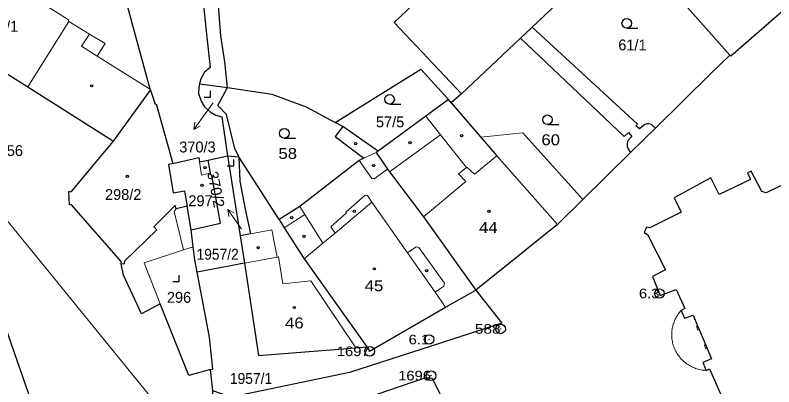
# Model space of a CAD drawing. Extents: x -679733 to -673243, y -1075091 to -1066557.
# Drawn here: x -676657.5 to -676538.9, y -1071507.3 to -1071449.2 of the extents above; entities that cross this region are included whole.
import ezdxf
from ezdxf.enums import TextEntityAlignment as Align

# ---------------------------------------------------------------- set-up
doc = ezdxf.new("R2010")
doc.units = 0
doc.header["$LTSCALE"] = 0.68
for name, color, linetype, lineweight in [('1', 7, 'Continuous', 25), ('13', 7, 'Continuous', 13), ('3', 7, 'Continuous', 25), ('4', 7, 'Continuous', 13), ('5', 7, 'Continuous', 25), ('7', 7, 'Continuous', 13), ('8', 7, 'Continuous', 25)]:
    doc.layers.add(name, color=color, linetype=linetype, lineweight=lineweight)
doc.layers.add('2', color=7, linetype='Continuous')

msp = doc.modelspace()

# ---------------------------------------------------------------- linework, layer by layer
at = {"layer": '1'}
for p, q in [((-676628.73, -1071459.98), (-676624.32, -1071460.51)), ((-676642.15, -1071468.89), (-676636.38, -1071460.95)), ((-676589.38, -1071462.9), (-676589.79, -1071462.4)), ((-676587.79, -1071461.53), (-676589.38, -1071462.9)), ((-676606.31, -1071466.64), (-676607.51, -1071466)), ((-676561.31, -1071470.64), (-676557.42, -1071466.86)), ((-676627.36, -1071471.86), (-676624.35, -1071471.19)), ((-676624.35, -1071471.19), (-676622.36, -1071483.7)), ((-676616.29, -1071481.17), (-676622.56, -1071471.37)), ((-676572.75, -1071481.92), (-676585.53, -1071492.18)), ((-676622.36, -1071483.7), (-676621.71, -1071487.97)), ((-676621.71, -1071487.97), (-676629.08, -1071489.37))]:
    msp.add_line(p, q, dxfattribs=at)
for points in [[(-676575.21, -1071422.22), (-676585.95, -1071432.82), (-676589.88, -1071436.78), (-676588.71, -1071438.04), (-676592.2, -1071441.42), (-676590.62, -1071443.1), (-676592.88, -1071445.22), (-676594.32, -1071443.69), (-676596.77, -1071446.05), (-676595.33, -1071447.58), (-676598.3, -1071450.36), (-676587.79, -1071461.53)], [(-676624.32, -1071460.51), (-676624.77, -1071456.53), (-676625.37, -1071452.45), (-676625.93, -1071445.76), (-676626.71, -1071437.13), (-676627.11, -1071434.06), (-676627.22, -1071431), (-676625.45, -1071424.7), (-676629.15, -1071423.95), (-676629.99, -1071425.14)], [(-676629.99, -1071425.14), (-676626.5, -1071425.54), (-676627.51, -1071429.11), (-676631.18, -1071428.42), (-676629.85, -1071430.36), (-676627.63, -1071452.18), (-676627.06, -1071457.4), (-676627.95, -1071458.12), (-676628.5, -1071459.17), (-676628.73, -1071459.98)], [(-676636.38, -1071460.95), (-676636.42, -1071460.8), (-676642.28, -1071439.33), (-676642.84, -1071437.27)], [(-676545.82, -1071455.5), (-676555.33, -1071444.77), (-676560.86, -1071438.5), (-676561.02, -1071438.3)], [(-676557.42, -1071466.86), (-676557.95, -1071466.4), (-676558.07, -1071466.32), (-676558.3, -1071466.23), (-676558.56, -1071466.19), (-676558.82, -1071466.22), (-676559.09, -1071466.31), (-676559.32, -1071466.47), (-676559.94, -1071467.01), (-676560.51, -1071466.49), (-676560.28, -1071466.24), (-676576.7, -1071451.11), (-676570.92, -1071445.57), (-676569.45, -1071444.14), (-676566.87, -1071441.72)], [(-676683.31, -1071443.03), (-676678.47, -1071446), (-676678.32, -1071445.78), (-676677.41, -1071446.35), (-676671.78, -1071449.97), (-676667.98, -1071452.47), (-676668.07, -1071452.62), (-676659.58, -1071457.99), (-676659.52, -1071457.9), (-676655.53, -1071460.4), (-676642.15, -1071468.89)], [(-676706.46, -1071448.39), (-676704.76, -1071448.03), (-676703.73, -1071447.81), (-676701.26, -1071447.54), (-676698.72, -1071447.92), (-676696.46, -1071448.78), (-676694.26, -1071449.98), (-676691.89, -1071451.57), (-676693.28, -1071454.07), (-676687.45, -1071458.85), (-676678.05, -1071467.82), (-676669.42, -1071477.57), (-676664.74, -1071483.89), (-676662.51, -1071488.58), (-676660.71, -1071493.4), (-676651.25, -1071520.53)], [(-676536.58, -1071447.6), (-676536.53, -1071447.7), (-676545.68, -1071455.62), (-676545.82, -1071455.5)], [(-676587.79, -1071461.53), (-676578.53, -1071452.8), (-676562.35, -1071468.16), (-676561.69, -1071467.58), (-676561.13, -1071468.18), (-676561.69, -1071468.71), (-676561.83, -1071469.03), (-676561.87, -1071469.31), (-676561.86, -1071469.73), (-676561.72, -1071470.13), (-676561.5, -1071470.46), (-676561.31, -1071470.64)], [(-676557.42, -1071466.86), (-676548.86, -1071458.37), (-676545.82, -1071455.5)], [(-676607.51, -1071466), (-676594.11, -1071457.66), (-676589.79, -1071462.4)], [(-676628.73, -1071459.98), (-676628.82, -1071460.51), (-676628.88, -1071461.45), (-676628.47, -1071462.65), (-676627.94, -1071463.57), (-676627.05, -1071464.32), (-676626.16, -1071464.83), (-676625.23, -1071465.11), (-676624.35, -1071471.19), (-676622.56, -1071471.37)], [(-676636.38, -1071460.95), (-676635.66, -1071463.14), (-676635.48, -1071463.1), (-676632.91, -1071472.41)], [(-676622.56, -1071471.37), (-676623.2, -1071470.06), (-676624.52, -1071464.72), (-676625.83, -1071463.35), (-676624.32, -1071460.51)], [(-676624.32, -1071460.51), (-676617.41, -1071461.57), (-676612.04, -1071463.56), (-676607.51, -1071466)], [(-676589.79, -1071462.4), (-676593.35, -1071465.01), (-676600.82, -1071470.47)], [(-676589.38, -1071462.9), (-676582.24, -1071471.2), (-676572.75, -1071481.92), (-676561.31, -1071470.64)], [(-676606.31, -1071466.64), (-676607.49, -1071468.2), (-676603.03, -1071471.58), (-676603.76, -1071471.92), (-676613.06, -1071479.12), (-676616.29, -1071481.17)], [(-676600.82, -1071470.47), (-676601.26, -1071470.14), (-676606.31, -1071466.64)], [(-676640.98, -1071488.07), (-676640.98, -1071487.71), (-676648.75, -1071478.84), (-676649.05, -1071478.85), (-676649.16, -1071476.79), (-676648.75, -1071476.77), (-676642.15, -1071468.89)], [(-676600.82, -1071470.47), (-676601.13, -1071470.7), (-676599.31, -1071473.3), (-676599.02, -1071473.71), (-676593.72, -1071480.71), (-676585.53, -1071492.18)], [(-676632.91, -1071472.41), (-676628.82, -1071471.47), (-676628.71, -1071472.16), (-676627.36, -1071471.86)], [(-676630.02, -1071482.74), (-676625.44, -1071481.71), (-676626.79, -1071474.25), (-676626.95, -1071474.15), (-676627.36, -1071471.86)], [(-676622.56, -1071471.37), (-676622.4, -1071475.15), (-676621.6, -1071479.52), (-676620.73, -1071483.38), (-676622.36, -1071483.7)], [(-676632.91, -1071472.41), (-676633.59, -1071472.56), (-676632.83, -1071476.98), (-676631.07, -1071476.67), (-676630.65, -1071479.08)], [(-676535.46, -1071474.69), (-676540.14, -1071476.96), (-676540.83, -1071476.76), (-676542.48, -1071473.58), (-676543.09, -1071473.88), (-676542.6, -1071474.91), (-676547.5, -1071477.26), (-676548.79, -1071474.64), (-676554.53, -1071477.75), (-676553.41, -1071480.02), (-676558.35, -1071482.47), (-676558.83, -1071482.37), (-676559.21, -1071483.18), (-676558.7, -1071483.47), (-676555.88, -1071489.02), (-676557.91, -1071490.05), (-676556.69, -1071493.04), (-676554.21, -1071492.06), (-676552.88, -1071495.05), (-676553.44, -1071495.37), (-676552.91, -1071496.58), (-676551.58, -1071496.09), (-676550.88, -1071497.75), (-676550.62, -1071498.35), (-676549.63, -1071500.7), (-676549.38, -1071501.29), (-676548.69, -1071502.91), (-676550.04, -1071503.48), (-676549.55, -1071504.72), (-676548.98, -1071504.49), (-676546.37, -1071510.5)], [(-676630.65, -1071479.08), (-676632.38, -1071479.48), (-676632.51, -1071478.95), (-676635.87, -1071482.28), (-676635.41, -1071482.76), (-676640.47, -1071487.67), (-676640.56, -1071488.12), (-676640.98, -1071488.07)], [(-676629.08, -1071489.37), (-676629.44, -1071487.46), (-676629.69, -1071485.41), (-676630.02, -1071482.74), (-676630.65, -1071479.08)], [(-676616.29, -1071481.17), (-676615.48, -1071482.43), (-676612.36, -1071487.31), (-676602.56, -1071501.05)], [(-676627.01, -1071504.59), (-676630.37, -1071505.54), (-676634.87, -1071494.32), (-676637.78, -1071495.87), (-676640.61, -1071489.82), (-676640.98, -1071488.07)], [(-676621.71, -1071487.97), (-676619.51, -1071502.38), (-676604.26, -1071501.2), (-676602.56, -1071501.05)], [(-676627.01, -1071504.59), (-676626.63, -1071504.55), (-676627.15, -1071499.52), (-676629.08, -1071489.37)], [(-676585.53, -1071492.18), (-676581.49, -1071497.33), (-676590.88, -1071500.43), (-676605.28, -1071505.07), (-676623.79, -1071508.92), (-676626.66, -1071507.94)], [(-676602.56, -1071501.05), (-676602.13, -1071501.74), (-676590.25, -1071494.84), (-676585.53, -1071492.18)], [(-676626.29, -1071515.38), (-676626.5, -1071515.56), (-676626.66, -1071507.94), (-676627.01, -1071504.59)], [(-676606.56, -1071510.38), (-676593.35, -1071505.84), (-676592.33, -1071505.91), (-676583.83, -1071523.22)]]:
    msp.add_lwpolyline(points, dxfattribs=at)
at = {"layer": '13'}
msp.add_lwpolyline([(-676572.75, -1071481.92), (-676568.81, -1071478.03), (-676578.19, -1071467.6), (-676584.73, -1071468.31), (-676582.24, -1071471.2)], close=True, dxfattribs=at)
at = {"layer": '3'}
for p, q in [((-676561.933, -1071451.25), (-676560.183, -1071451.25)), ((-676599.013, -1071463.14), (-676597.263, -1071463.14)), ((-676574.323, -1071466.32), (-676572.573, -1071466.32)), ((-676615.463, -1071468.44), (-676613.713, -1071468.44))]:
    msp.add_line(p, q, dxfattribs=at)
for points in [[(-676628.011, -1071462.03), (-676627.01, -1071462.03), (-676627.01, -1071461.03)], [(-676624.371, -1071472.78), (-676623.37, -1071472.78), (-676623.37, -1071471.78)], [(-676632.911, -1071490.85), (-676631.91, -1071490.85), (-676631.91, -1071489.85)]]:
    msp.add_lwpolyline(points, dxfattribs=at)
for centre in [(-676561.9329, -1071450.4998), (-676599.0129, -1071462.3898), (-676574.3229, -1071465.5698), (-676615.4629, -1071467.6898)]:
    msp.add_circle(centre, 0.75, dxfattribs=at)
at = {"layer": '4'}
for p, q in [((-676652.91, -1071447.63), (-676649.19, -1071449.94)), ((-676655.53, -1071460.4), (-676649.14, -1071450.24)), ((-676649.19, -1071449.94), (-676649.14, -1071450.24)), ((-676649.14, -1071450.24), (-676645.94, -1071452.19)), ((-676578.53, -1071452.8), (-676576.7, -1071451.11)), ((-676647.19, -1071454.08), (-676645.94, -1071452.19)), ((-676645.94, -1071452.19), (-676643.49, -1071453.65)), ((-676644.72, -1071455.62), (-676647.19, -1071454.08)), ((-676643.49, -1071453.65), (-676644.72, -1071455.62)), ((-676644.72, -1071455.62), (-676637.62, -1071460.05)), ((-676637.62, -1071460.05), (-676636.42, -1071460.8)), ((-676591.06, -1071467.9), (-676593.35, -1071465.01)), ((-676599.02, -1071473.71), (-676591.06, -1071467.9)), ((-676586.99, -1071473.05), (-676591.06, -1071467.9)), ((-676603.03, -1071471.58), (-676601.13, -1071470.7)), ((-676601.77, -1071474.75), (-676603.76, -1071471.92)), ((-676585.73, -1071474.09), (-676582.24, -1071471.2)), ((-676628.39, -1071474.21), (-676628.71, -1071472.16)), ((-676599.31, -1071473.3), (-676601.44, -1071474.79)), ((-676588.22, -1071474.02), (-676586.99, -1071473.05)), ((-676586.99, -1071473.05), (-676586.91, -1071472.99)), ((-676586.91, -1071472.99), (-676585.73, -1071474.09)), ((-676628.39, -1071474.21), (-676627.38, -1071473.98)), ((-676627.38, -1071473.98), (-676626.95, -1071474.15)), ((-676587.07, -1071475.2), (-676588.22, -1071474.02)), ((-676601.44, -1071474.79), (-676601.77, -1071474.75)), ((-676593.72, -1071480.71), (-676587.07, -1071475.2)), ((-676636.76, -1071508.39), (-676663.26, -1071475.84)), ((-676602.83, -1071477.37), (-676605.85, -1071480.02)), ((-676602.47, -1071477.42), (-676602.83, -1071477.37)), ((-676601.76, -1071478.44), (-676602.47, -1071477.42)), ((-676612.26, -1071480.39), (-676613.06, -1071479.12)), ((-676607.52, -1071483.26), (-676601.76, -1071478.44)), ((-676601.76, -1071478.44), (-676596.2, -1071486.36)), ((-676632.38, -1071479.48), (-676632.67, -1071479.89)), ((-676632.67, -1071479.89), (-676631.21, -1071485.9)), ((-676612.26, -1071480.39), (-676615.48, -1071482.43)), ((-676609.43, -1071484.86), (-676612.26, -1071480.39)), ((-676605.76, -1071480.13), (-676608.21, -1071482.28)), ((-676605.85, -1071480.02), (-676605.76, -1071480.13)), ((-676617.44, -1071482.74), (-676620.73, -1071483.38)), ((-676616.56, -1071487.01), (-676617.44, -1071482.74)), ((-676608.21, -1071482.28), (-676607.52, -1071483.26)), ((-676609.43, -1071484.86), (-676607.52, -1071483.26)), ((-676612.36, -1071487.31), (-676609.43, -1071484.86)), ((-676631.21, -1071485.9), (-676637.38, -1071487.9)), ((-676631.21, -1071485.9), (-676629.69, -1071485.41)), ((-676596.2, -1071486.36), (-676594.86, -1071485.42)), ((-676596.2, -1071486.36), (-676591.88, -1071492.52)), ((-676594.86, -1071485.42), (-676594.45, -1071485.5)), ((-676594.45, -1071485.5), (-676590.42, -1071491.12)), ((-676621.71, -1071487.97), (-676616.56, -1071487.01)), ((-676616.37, -1071486.98), (-676616.56, -1071487.01)), ((-676616.37, -1071486.98), (-676615.72, -1071491.19)), ((-676634.87, -1071494.32), (-676637.38, -1071487.9)), ((-676615.72, -1071491.19), (-676611.3, -1071490.73)), ((-676611.3, -1071490.73), (-676604.26, -1071501.2)), ((-676590.51, -1071491.56), (-676591.88, -1071492.52)), ((-676590.42, -1071491.12), (-676590.51, -1071491.56)), ((-676591.88, -1071492.52), (-676590.25, -1071494.84)), ((-676550.88, -1071497.75), (-676551.06, -1071497.83)), ((-676551.06, -1071497.83), (-676550.81, -1071498.43)), ((-676550.81, -1071498.43), (-676550.62, -1071498.35)), ((-676549.63, -1071500.7), (-676549.81, -1071500.78)), ((-676549.81, -1071500.78), (-676549.56, -1071501.37)), ((-676549.56, -1071501.37), (-676549.38, -1071501.29))]:
    msp.add_line(p, q, dxfattribs=at)
msp.add_lwpolyline([(-676553.44, -1071495.37), (-676553.578, -1071495.526), (-676553.71, -1071495.687), (-676553.836, -1071495.852), (-676553.955, -1071496.023), (-676554.068, -1071496.197), (-676554.175, -1071496.376), (-676554.275, -1071496.558), (-676554.368, -1071496.744), (-676554.454, -1071496.934), (-676554.532, -1071497.126), (-676554.604, -1071497.322), (-676554.668, -1071497.519), (-676554.725, -1071497.72), (-676554.775, -1071497.922), (-676554.816, -1071498.125), (-676554.851, -1071498.331), (-676554.877, -1071498.537), (-676554.896, -1071498.744), (-676554.907, -1071498.952), (-676554.91, -1071499.16), (-676554.906, -1071499.368), (-676554.893, -1071499.576), (-676554.874, -1071499.783), (-676554.846, -1071499.989), (-676554.811, -1071500.194), (-676554.768, -1071500.397), (-676554.717, -1071500.599), (-676554.659, -1071500.799), (-676554.594, -1071500.996), (-676554.521, -1071501.191), (-676554.441, -1071501.383), (-676554.354, -1071501.572), (-676554.26, -1071501.758), (-676554.159, -1071501.94), (-676554.052, -1071502.118), (-676553.938, -1071502.292), (-676553.817, -1071502.461), (-676553.69, -1071502.626), (-676553.558, -1071502.786), (-676553.419, -1071502.942), (-676553.274, -1071503.091), (-676553.125, -1071503.236), (-676552.969, -1071503.374), (-676552.809, -1071503.507), (-676552.644, -1071503.634), (-676552.475, -1071503.754), (-676552.301, -1071503.868), (-676552.123, -1071503.975), (-676551.94, -1071504.076), (-676551.755, -1071504.17), (-676551.566, -1071504.257), (-676551.374, -1071504.337), (-676551.179, -1071504.409), (-676550.981, -1071504.474), (-676550.781, -1071504.532), (-676550.58, -1071504.583), (-676550.376, -1071504.625), (-676550.171, -1071504.661), (-676549.965, -1071504.688), (-676549.758, -1071504.708), (-676549.55, -1071504.72)], dxfattribs=at)
at = {"layer": '5'}
for centre in [(-676645.5668, -1071460.2692), (-676587.7568, -1071468.0392), (-676604.2968, -1071469.2892), (-676595.8268, -1071469.1392), (-676627.8568, -1071473.0592), (-676601.4968, -1071472.7192), (-676640.0168, -1071474.4092), (-676628.3468, -1071475.7992), (-676604.5068, -1071479.8592), (-676583.4768, -1071479.8792), (-676614.2968, -1071480.8792), (-676612.3968, -1071483.7792), (-676619.5568, -1071485.5392), (-676601.3768, -1071488.8592), (-676593.1968, -1071489.1592), (-676613.8968, -1071494.8992)]:
    msp.add_circle(centre, 0.175, dxfattribs=at)
at = {"layer": '7'}
for p, q in [((-676629.624, -1071467.068), (-676628.63, -1071466.552)), ((-676624.291, -1071479.592), (-676624.127, -1071480.699))]:
    msp.add_line(p, q, dxfattribs=at)
for points in [[(-676626.6, -1071462.91), (-676627.86, -1071464.64), (-676629.624, -1071467.068), (-676629.44, -1071465.963)], [(-676622.14, -1071482.67), (-676622.57, -1071482.05), (-676624.291, -1071479.592), (-676623.307, -1071480.125)]]:
    msp.add_lwpolyline(points, dxfattribs=at)
at = {"layer": '8'}
for centre, radius in [((-676556.83, -1071492.7098), 0.75), ((-676556.83, -1071492.7098), 0.03), ((-676581.66, -1071498.2398), 0.75), ((-676581.66, -1071498.2398), 0.03), ((-676592.83, -1071499.8998), 0.75), ((-676592.83, -1071499.8998), 0.03), ((-676602.13, -1071501.7398), 0.75), ((-676602.13, -1071501.7398), 0.03), ((-676592.54, -1071505.5398), 0.75), ((-676592.54, -1071505.5398), 0.03)]:
    msp.add_circle(centre, radius, dxfattribs=at)

# ---------------------------------------------------------------- texts
at = {"layer": '2'}
for s, p in [('298/1', (-676662.74, -1071451.81)), ('61/1', (-676563.26, -1071454.729)), ('1956', (-676661.37, -1071471.239)), ('298/2', (-676643.49, -1071478.1)), ('297', (-676630.46, -1071479.07)), ('296', (-676633.82, -1071494.16))]:
    msp.add_text(s, height=1.7, dxfattribs=at).set_placement(p)
msp.add_text('57/5', height=1.7, dxfattribs=at).set_placement((-676598.93, -1071466.749), align=Align.CENTER)
for s, width, p in [('60', 1.15, (-676575.28, -1071469.54)), ('58', 1.15, (-676616.38, -1071471.68)), ('44', 1.15, (-676585.03, -1071483.259)), ('1957/2', 0.95, (-676629.19, -1071487.43)), ('45', 1.15, (-676602.9, -1071492.35)), ('46', 1.15, (-676615.35, -1071498.16)), ('1957/1', 0.95, (-676623.97, -1071506.83))]:
    msp.add_text(s, height=1.7, dxfattribs=dict(at, width=width)).set_placement(p)
msp.add_text('370/3', height=1.7, dxfattribs=at).set_placement((-676626.199, -1071470.673), align=Align.RIGHT)
msp.add_text('370/2', height=1.7, rotation=281, dxfattribs=at).set_placement((-676626.4417, -1071479.4076), align=Align.RIGHT)
at = {"layer": '8'}
for s, width, p in [('6.3', 1.15, (-676556.829, -1071493.46)), ('588', 1.2, (-676581.66, -1071498.99)), ('6.1', 1.15, (-676592.829, -1071500.649)), ('1697', 1.15, (-676602.129, -1071502.49)), ('1696', 1.15, (-676592.539, -1071506.29))]:
    msp.add_text(s, height=1.5, dxfattribs=dict(at, width=width)).set_placement(p, align=Align.RIGHT)

doc.saveas('drawing.dxf')
